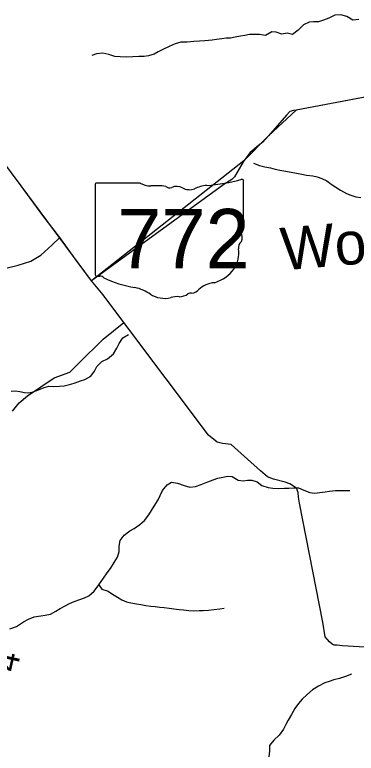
# Model space of a CAD drawing. Extents: x 0 to 34, y 0 to 22.
# Drawn here: x 5.001 to 5.759, y 15.038 to 16.678 of the extents above; entities that cross this region are included whole.
import ezdxf

# ---------------------------------------------------------------- set-up
doc = ezdxf.new("R2010")
doc.units = 0
for name, color, linetype in [('Default', 7, 'Continuous'), ('GM_X_County_Road', 7, 'Continuous'), ('GM_X_County_Road_Text', 7, 'Continuous'), ('GM_X_Major_River', 7, 'Continuous'), ('GM_X_Minor_River', 7, 'Continuous'), ('GM_X_Minor_River_Text', 7, 'Continuous'), ('GM_X_State_Location', 7, 'Continuous'), ('GM_X_State_Route', 7, 'Continuous'), ('GM_X_State_Shield', 7, 'Continuous'), ('GM_X_Township_Road', 7, 'Continuous')]:
    doc.layers.add(name, color=color, linetype=linetype)

msp = doc.modelspace()

# ---------------------------------------------------------------- linework, layer by layer
at = {"layer": 'Default'}
for p, q in [((6.0769, 16.552), (5.6252, 16.4666)), ((5.6252, 16.4666), (5.5636, 16.4096)), ((5.5636, 16.4096), (5.5094, 16.354)), ((5.0144, 16.2982), (4.9717, 16.3565)), ((5.5094, 16.354), (5.1712, 16.0875)), ((5.1712, 16.0875), (5.0144, 16.2982))]:
    msp.add_line(p, q, dxfattribs=at)
at = {"layer": 'GM_X_County_Road'}
for points in [[(5.8629, 15.2685), (5.7283, 15.2765), (5.7166, 15.2782), (5.7098, 15.2782), (5.7053, 15.2802), (5.6993, 15.2852), (5.6896, 15.2963), (5.6846, 15.329), (5.633, 15.5931), (5.6305, 15.6067), (5.6295, 15.617), (5.6262, 15.6269), (5.6115, 15.6362), (5.601, 15.6401), (5.5753, 15.6465), (5.5614, 15.6523), (5.5464, 15.6654), (5.4962, 15.7104), (5.4813, 15.7238), (5.462, 15.726), (5.4499, 15.7287), (5.4304, 15.7445), (5.2429, 15.9949), (5.1967, 16.0566), (5.1712, 16.0875)], [(4.9957, 15.7976), (5.0103, 15.8165), (5.029, 15.8322), (5.0877, 15.8718), (5.1226, 15.8843), (5.1429, 15.9046), (5.1968, 15.9579), (5.2429, 15.9949)]]:
    msp.add_lwpolyline(points, dxfattribs=at)
at = {"layer": 'GM_X_Major_River'}
msp.add_lwpolyline([(5.7644, 16.6677), (5.7515, 16.6663), (5.7376, 16.6745), (5.7244, 16.6784), (5.7115, 16.6774), (5.6978, 16.6711), (5.686, 16.6664), (5.6753, 16.6627), (5.6636, 16.6624), (5.6541, 16.6622), (5.6415, 16.6563), (5.63, 16.6443), (5.6174, 16.6349), (5.6057, 16.6373), (5.5936, 16.6356), (5.5811, 16.6399), (5.5713, 16.6404), (5.5575, 16.6326), (5.5439, 16.6347), (5.5311, 16.6348), (5.5216, 16.6346), (5.5113, 16.6324), (5.5018, 16.6306), (5.4897, 16.6285), (5.4798, 16.6267), (5.47, 16.6261), (5.4605, 16.6247), (5.4484, 16.6237), (5.4389, 16.6223), (5.4222, 16.6206), (5.4104, 16.62), (5.3979, 16.619), (5.3835, 16.6173), (5.3691, 16.6178), (5.357, 16.6142), (5.3436, 16.6079), (5.3295, 16.6012), (5.3192, 16.596), (5.3097, 16.5908), (5.2975, 16.5872), (5.288, 16.5858), (5.2759, 16.5855), (5.2627, 16.5849), (5.2483, 16.5844), (5.2346, 16.5849), (5.2229, 16.5854), (5.2093, 16.5905), (5.1961, 16.5934), (5.1821, 16.592), (5.1718, 16.5876)], dxfattribs=at)
at = {"layer": 'GM_X_Minor_River'}
for points in [[(5.5308, 16.3489), (5.5437, 16.3439), (5.5555, 16.3409), (5.5687, 16.3382), (5.579, 16.3355), (5.5892, 16.3333), (5.6021, 16.331), (5.6139, 16.3287), (5.6264, 16.3268), (5.6381, 16.3241), (5.6484, 16.3222), (5.6624, 16.3203), (5.6723, 16.3184), (5.6821, 16.315), (5.6931, 16.3097), (5.7034, 16.3024), (5.7136, 16.2952), (5.7238, 16.2884), (5.7371, 16.2811), (5.7466, 16.2773), (5.7576, 16.2743), (5.7693, 16.2728)], [(4.9927, 15.8425), (5.0022, 15.8433), (5.012, 15.8417), (5.0223, 15.8391), (5.0318, 15.8383), (5.0416, 15.841), (5.053, 15.8452), (5.0659, 15.8501), (5.0762, 15.8531), (5.086, 15.8528), (5.0997, 15.8531), (5.1103, 15.8543), (5.1247, 15.8577), (5.1346, 15.8607), (5.1463, 15.8649), (5.1562, 15.868), (5.1698, 15.8759), (5.1774, 15.8866), (5.1831, 15.8968), (5.1938, 15.9083), (5.2067, 15.914), (5.2199, 15.9254), (5.2275, 15.9379), (5.2321, 15.9482), (5.2404, 15.9607), (5.253, 15.9683)], [(4.9894, 15.314), (5.0042, 15.3197), (5.0201, 15.3296), (5.0311, 15.3357), (5.0436, 15.3406), (5.0584, 15.3433), (5.0679, 15.3444), (5.0801, 15.3471), (5.0918, 15.3536), (5.1013, 15.3593), (5.1123, 15.365), (5.1222, 15.3707), (5.1324, 15.3752), (5.1449, 15.3794), (5.1556, 15.3828), (5.165, 15.3874), (5.1768, 15.398), (5.187, 15.4117), (5.1977, 15.4265), (5.206, 15.4383), (5.2129, 15.4482), (5.2216, 15.4615), (5.2284, 15.4737), (5.2322, 15.4862), (5.2326, 15.4976), (5.2349, 15.5106), (5.2436, 15.5227), (5.2558, 15.5322), (5.2656, 15.5375), (5.2781, 15.5463), (5.2888, 15.555), (5.2979, 15.5676), (5.3043, 15.5775), (5.3104, 15.587), (5.3191, 15.6006), (5.3237, 15.6102), (5.3286, 15.6219), (5.3389, 15.6345), (5.3484, 15.6398), (5.362, 15.6379), (5.3764, 15.633), (5.3893, 15.6292), (5.4018, 15.6303), (5.4144, 15.6349), (5.4292, 15.6406), (5.4413, 15.6451), (5.4515, 15.6489), (5.4622, 15.6512), (5.4735, 15.6531), (5.483, 15.6527), (5.4967, 15.6447), (5.5077, 15.6428), (5.5171, 15.6443), (5.527, 15.6447), (5.5384, 15.6405), (5.5494, 15.6325), (5.5634, 15.6284), (5.5737, 15.6268), (5.5865, 15.6261), (5.5994, 15.6265), (5.6093, 15.6268), (5.6199, 15.6276), (5.6302, 15.6276), (5.6427, 15.6223), (5.6556, 15.6169), (5.6662, 15.6158), (5.6897, 15.6188), (5.6996, 15.62), (5.7125, 15.6215), (5.7227, 15.6219), (5.7447, 15.6219)], [(5.187, 15.4117), (5.1939, 15.4026), (5.2079, 15.398), (5.2178, 15.3916), (5.2288, 15.3843), (5.2386, 15.379), (5.2489, 15.3744), (5.2583, 15.3718), (5.2708, 15.3695), (5.2803, 15.368), (5.2917, 15.3661), (5.3023, 15.3649), (5.3122, 15.3638), (5.3228, 15.3626), (5.3323, 15.3615), (5.3433, 15.36), (5.3539, 15.3588), (5.3657, 15.3573), (5.3755, 15.3562), (5.3869, 15.355), (5.3979, 15.3546), (5.4097, 15.355), (5.4191, 15.355), (5.4309, 15.3554), (5.4434, 15.3569), (5.4559, 15.3588), (5.4658, 15.36)], [(5.7479, 15.2139), (5.7346, 15.2082), (5.7217, 15.2037), (5.7088, 15.2006), (5.6986, 15.1976), (5.6887, 15.1942), (5.6747, 15.1869), (5.6618, 15.1786), (5.6493, 15.1679), (5.639, 15.158), (5.6307, 15.1485), (5.6223, 15.1375), (5.6147, 15.1242), (5.6079, 15.1117), (5.6026, 15.1014), (5.5973, 15.0915), (5.5874, 15.0782), (5.576, 15.0668), (5.5665, 15.0554), (5.5661, 15.0429), (5.5646, 15.0299)]]:
    msp.add_lwpolyline(points, dxfattribs=at)
at = {"layer": 'GM_X_State_Route'}
msp.add_lwpolyline([(6.0769, 16.552), (5.6252, 16.4666), (5.6198, 16.4655), (5.6114, 16.4635), (5.604, 16.4557), (5.5636, 16.4096), (5.5511, 16.3955), (5.5414, 16.3881), (5.5235, 16.3722), (5.5094, 16.354), (5.4886, 16.3183), (5.4828, 16.3128), (5.465, 16.3011), (5.1712, 16.0875), (5.1345, 16.1363), (5.1003, 16.1837), (5.0631, 16.2322), (5.0144, 16.2982), (4.9717, 16.3565)], dxfattribs=at)
at = {"layer": 'GM_X_State_Shield'}
for p, q in [((5.5086, 16.2049), (5.5086, 16.3096)), ((5.179, 16.3012), (5.179, 16.101)), ((5.2787, 16.3046), (5.1822, 16.3046)), ((5.5085, 16.2049), (5.5086, 16.2049))]:
    msp.add_line(p, q, dxfattribs=at)
for centre, major_axis, start_param, end_param in [((5.3912, 16.5774), (0.3495, 0), 4.814394, 5.042369), ((5.5049, 16.31), (0.00367, 0), 6.141152, 7.989035), ((5.1828, 16.3016), (0.00382, 0), 1.712693, 3.28349), ((5.3017, 16.3278), (0.037, 0), 4.042523, 4.731795), ((5.314, 16.1923), (0.133, 0), 1.404758, 1.657858), ((5.3442, 16.3026), (0.0107, 0), 3.836095, 5.185415), ((5.3599, 16.2795), (0.0222, 0), 0.950623, 2.079405), ((5.3886, 16.3112), (0.0267, 0), 4.081561, 5.145723), ((5.4357, 16.2435), (0.0703, 0), 1.699011, 2.107814), ((5.5077, 16.1972), (0.00568, 0), 1.883978, 3.671073), ((5.4716, 16.184), (0.0341, 0), 5.934695, 6.695948), ((5.5047, 16.2045), (0.00393, 0), 5.05454, 6.418171), ((5.5217, 16.1611), (0.0248, 0), 2.387724, 3.262537), ((5.4107, 16.1478), (0.0874, 0), 5.101752, 6.440018), ((5.1828, 16.1006), (0.00385, 0), 3.00124, 4.508301), ((5.1834, 16.1211), (0.0294, 0), 4.665946, 4.897461), ((5.1894, 16.0895), (0.0106, 0), 0.519207, 1.627899), ((5.3232, 16.2693), (0.2524, 0), 4.195997, 4.488961), ((5.4476, 16.0449), (0.0479, 0), 1.647645, 2.488434), ((5.248, 16.0111), (0.079, 0), 0.823519, 1.323587), ((5.3901, 16.0541), (0.00752, 0), 1.147584, 2.315152), ((5.3869, 16.0816), (0.0282, 0), 4.937069, 5.64225), ((5.3334, 16.0885), (0.0501, 0), 4.026481, 4.996735), ((5.3623, 16.0193), (0.0412, 0), 1.495662, 1.94098), ((5.366, 16.0735), (0.0267, 0), 4.691044, 5.507374)]:
    msp.add_ellipse(centre, major_axis=major_axis, ratio=0.8, start_param=start_param, end_param=end_param, dxfattribs=at)
at = {"layer": 'GM_X_Township_Road'}
msp.add_lwpolyline([(4.5464, 15.8674), (4.5524, 15.8796), (4.5638, 15.9007), (4.5736, 15.9192), (4.5815, 15.9299), (4.5907, 15.9408), (4.603, 15.9543), (4.6206, 15.9731), (4.703, 16.0397), (4.7609, 16.0755), (4.7917, 16.0953), (4.8069, 16.1042), (4.8179, 16.109), (4.8622, 16.1063), (4.9287, 16.107), (4.9749, 16.1141), (5.0079, 16.1221), (5.036, 16.1313), (5.0581, 16.1447), (5.0825, 16.1664), (5.1003, 16.1837)], dxfattribs=at)

# ---------------------------------------------------------------- texts
at = {"layer": 'GM_X_County_Road_Text'}
msp.add_text('4', height=0.0568, rotation=77.5821, dxfattribs=at).set_placement((5.0045, 15.2158))
at = {"layer": 'GM_X_Minor_River_Text'}
msp.add_text('Wolf', height=0.09469, rotation=4.9696, dxfattribs=at).set_placement((5.5953, 16.1103))
at = {"layer": 'GM_X_State_Location'}
for s in ['s', 'r']:
    msp.add_text(s, height=0.000189, dxfattribs=at).set_placement((5.3401, 16.1878))
msp.add_text('772', height=0.000189, rotation=0, dxfattribs=at).set_placement((5.2732, 16.174))
at = {"layer": 'GM_X_State_Shield'}
msp.add_text('772', height=0.13184, dxfattribs=at).set_placement((5.228, 16.1152))

doc.saveas('drawing.dxf')
